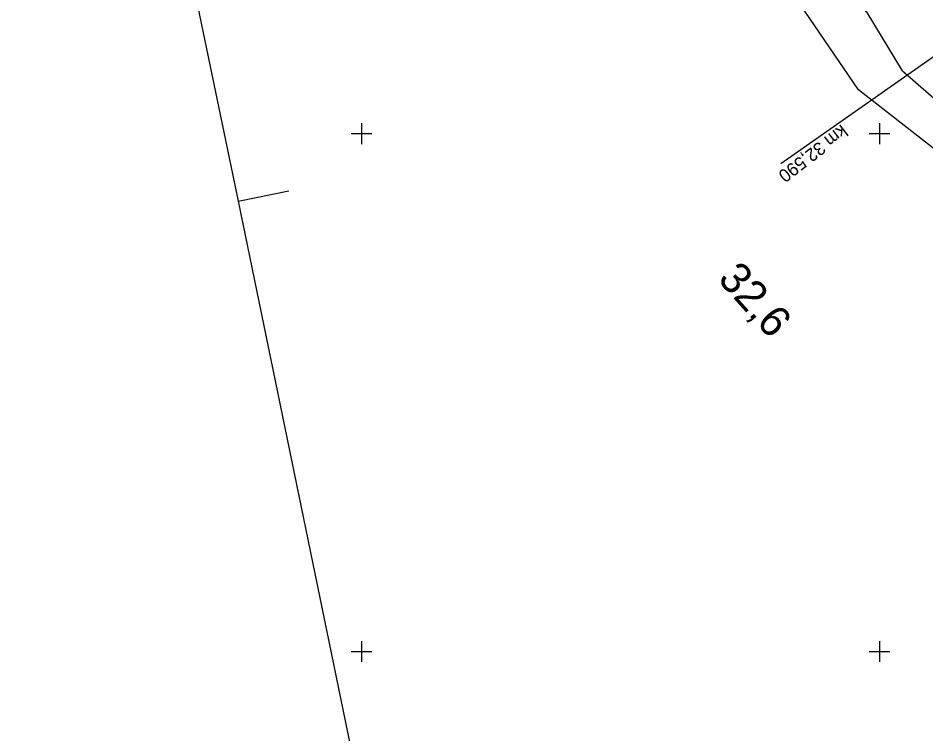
# Model space of a CAD drawing. Extents: x -804166 to -803706, y -1151030 to -1150147.
# Drawn here: x -804166.3 to -803991, y -1150515.9 to -1150377.7 of the extents above; entities that cross this region are included whole.
import ezdxf

# ---------------------------------------------------------------- set-up
doc = ezdxf.new("R2010")
doc.units = 0
for name, color, linetype in [('0381KM032-037P - Vrstva 3', 7, 'Continuous'), ('0381KM032-037P - Vrstva 49', 7, 'Continuous'), ('0381KM032-037P - Vrstva 7', 7, 'Continuous'), ('formát', 7, 'Continuous'), ('hran DP - hran DP', 7, 'Continuous'), ('krizky_1000 - Vrstva 1', 7, 'Continuous')]:
    doc.layers.add(name, color=color, linetype=linetype)

msp = doc.modelspace()

# ---------------------------------------------------------------- linework, layer by layer
at = {"layer": '0381KM032-037P - Vrstva 3'}
msp.add_line((-803980.37, -1150378.68), (-804019.01, -1150405.81), dxfattribs=at)
at = {"layer": '0381KM032-037P - Vrstva 49'}
for points in [[(-803995.51, -1150387.87), (-804002.35, -1150376.64), (-804007.46, -1150372.51), (-804011.72, -1150371.94), (-804015.88, -1150373.24)], [(-803995.51, -1150387.87), (-803978.95, -1150402.37), (-803967.97, -1150412.01), (-803952.57, -1150434.32)]]:
    msp.add_lwpolyline(points, dxfattribs=at)
at = {"layer": 'formát'}
for p, q in [((-804166.3, -1150207.4), (-804123.84, -1150413.06)), ((-804123.84, -1150413.06), (-804114.04, -1150411.04)), ((-804123.84, -1150413.06), (-804081.38, -1150618.72))]:
    msp.add_line(p, q, dxfattribs=at)
at = {"layer": 'hran DP - hran DP'}
for p, q in [((-804004.05, -1150391.51), (-804033.86, -1150347.88)), ((-803965.92, -1150421.41), (-804004.05, -1150391.51))]:
    msp.add_line(p, q, dxfattribs=at)
at = {"layer": 'krizky_1000 - Vrstva 1'}
for points in [[(-804100, -1150398), (-804100, -1150402)], [(-804000, -1150398), (-804000, -1150402)], [(-804102, -1150400), (-804098, -1150400)], [(-804002, -1150400), (-803998, -1150400)], [(-804100, -1150498), (-804100, -1150502)], [(-804000, -1150498), (-804000, -1150502)], [(-804102, -1150500), (-804098, -1150500)], [(-804002, -1150500), (-803998, -1150500)]]:
    msp.add_lwpolyline(points, dxfattribs=at)

# ---------------------------------------------------------------- texts
at = {"layer": '0381KM032-037P - Vrstva 3'}
msp.add_text('km 32,590', height=2.5, rotation=217.4866, dxfattribs=at).set_placement((-804007.35, -1150398.11))
at = {"layer": '0381KM032-037P - Vrstva 7'}
msp.add_text('32,6', height=6, rotation=311.8828, dxfattribs=at).set_placement((-804031.4, -1150428.19))

doc.saveas('drawing.dxf')
